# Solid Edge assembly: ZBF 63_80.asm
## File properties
Title: Zylinder
Author: bmolnar
Template: iso metric assembly.asm
Last saved by: bmolnar
Revision: 16
Application: Solid Edge
Username: bmolnar
Dokumentum tartalom típus: 1
Document Number: ZBF 63/80
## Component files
Profilrohr.par
Kolbenstange.par
Kit.par
Mutter.par
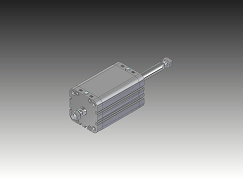
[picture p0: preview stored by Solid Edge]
